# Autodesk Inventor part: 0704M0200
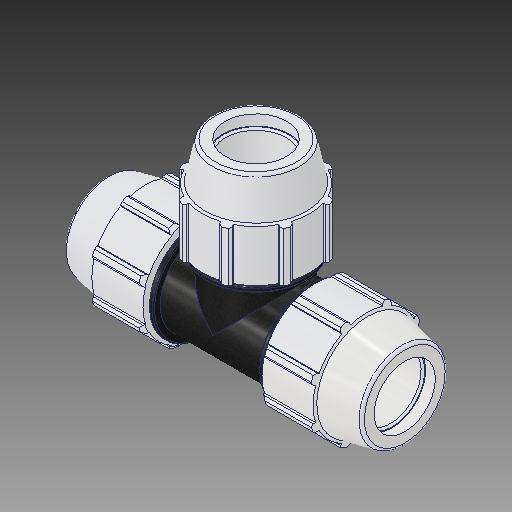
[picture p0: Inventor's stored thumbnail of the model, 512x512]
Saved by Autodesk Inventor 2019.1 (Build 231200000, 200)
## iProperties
Created: 2017-02
Part Number: 0704M0200
Material: PVC-Piping
Description: PLASSON TEE 2'' - 2'' - 2''
Document SubType Name: Modeling
Designer: KIM
Mass: 92.6774 g
Surface Area: 199.44 cm^2
Volume: 66.1981 cm^3
Density: 1.4 g/cm^3
Appearance: PTFE
Author: KIM
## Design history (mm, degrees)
derived "0704M0.ipt"
feature "Solid1::0704M0.ipt"
tag "TaggingFeature1"
body "Solid1"
other parameters: "d2" = 60.1, "d4" = 12.17083, "d5" = 36.5125, "d7" = 113.03, "d11" = 4.86833, "d13" = 120 deg, "d14" = 84.14, "d15" = 12 deg, "d16" = 98.3361, "d18" = 3.005, "d19" = 35 deg, "d20" = 17.5 deg, "d21" = 105.1179, "d23" = 0, "d25" = 360 deg, "d27" = 2.2606, "d33" = 1.202, "d42" = 51.1175, "d43" = 3.3909, "d46" = 1.803, "d63" = 108.966, "d67" = 84.7725, "d76" = 60.1, "d77" = 113.03, "d78" = 12 deg, "d79" = 146.05, "d80" = 120 deg, "d81" = 84.14, "d82" = 12.17083, "d85" = 84.7725, "d86" = 98.3361, "d87" = 4.86833, "d88" = 4.86833, "d89" = 36.5125, "d90" = 51.1175, "d96" = 14.605, "d98" = 105.1179, "d99" = 35 deg, "d100" = 17.5 deg, "d102" = 0, "d103" = 2.2606, "d107" = 360 deg, "d109" = 1.803, "d112" = 3.005, "d118" = 360 deg, "d121" = 0, "d128" = 292.1, "d131" = 54.09, "d132" = 54.09, "d133" = 108.966, "d134" = 2.17932, "d135" = 14.605, "d152" = 0, "d154" = 0, "d156" = 0, "d158" = 0, "d_" = 60.1, "E_" = 113.03, "A_" = 146.05, "l_" = 108.966, "H_" = 292.1
